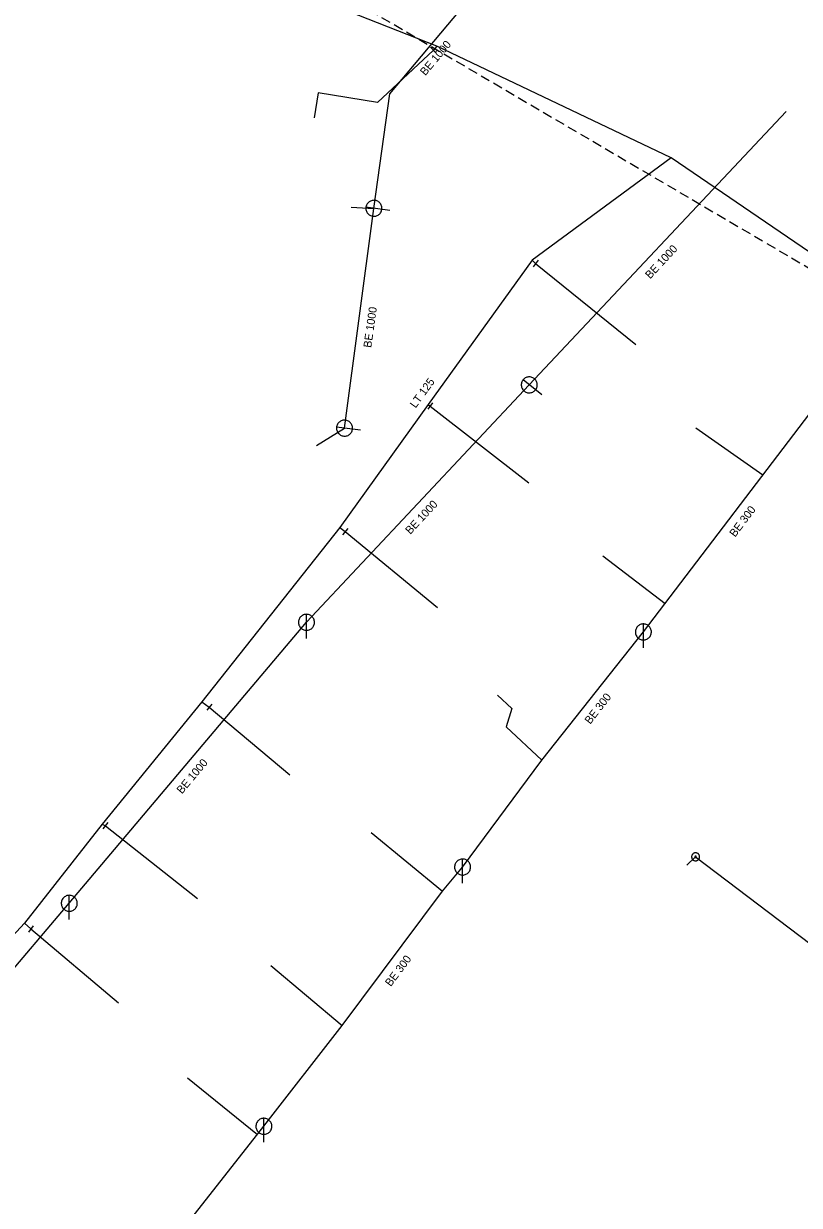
# Model space of a CAD drawing. Extents: x -791337 to -790755, y -988454 to -987923.
# Drawn here: x -790949.7 to -790852.8, y -988262.8 to -988115.1 of the extents above; entities that cross this region are included whole.
import ezdxf

# ---------------------------------------------------------------- set-up
doc = ezdxf.new("R2010")
doc.units = 0
doc.header["$LTSCALE"] = 0.4
doc.linetypes.add('MEDIUM_DASHED', pattern=[4.5, 3, -1.5])
for name, color, linetype, lineweight in [('1', 7, 'Continuous', 13), ('11', 7, 'Continuous', 13), ('13', 7, 'Continuous', 13), ('14', 7, 'Continuous', 25), ('17', 7, 'Continuous', 25), ('22', 7, 'Continuous', 13), ('34', 7, 'Continuous', 13), ('47', 7, 'Continuous', 13), ('63', 7, 'MEDIUM_DASHED', 25)]:
    doc.layers.add(name, color=color, linetype=linetype, lineweight=lineweight)

msp = doc.modelspace()

# ---------------------------------------------------------------- linework, layer by layer
at = {"layer": '11'}
for p, q in [((-790908.772, -988138.055), (-790905.94, -988138.22)), ((-790913.105, -988167.839), (-790909.605, -988165.675)), ((-790865.701, -988165.618), (-790857.318, -988171.518)), ((-790877.322, -988181.627), (-790869.546, -988187.578)), ((-790906.261, -988216.18), (-790897.349, -988223.506)), ((-790918.802, -988232.798), (-790909.899, -988240.304)), ((-790929.23, -988246.811), (-790920.498, -988253.919))]:
    msp.add_line(p, q, dxfattribs=at)
msp.add_lwpolyline([(-790890.491, -988199.037), (-790888.688, -988200.703), (-790889.381, -988202.993), (-790884.943, -988207.155)], dxfattribs=at)
at = {"layer": '13'}
for p, q in [((-790898.061, -988117.949), (-790898.489, -988118.469)), ((-790886.164, -988144.675), (-790885.719, -988145.118)), ((-790885.719, -988145.118), (-790873.182, -988155.239)), ((-790898.901, -988162.913), (-790886.583, -988172.519)), ((-790910.179, -988178.094), (-790909.519, -988178.599)), ((-790909.519, -988178.599), (-790897.998, -988188.059)), ((-790927.416, -988199.874), (-790926.509, -988200.529)), ((-790926.509, -988200.529), (-790916.436, -988208.971)), ((-790939.489, -988215.339), (-790927.989, -988224.438)), ((-790865.725, -988219.221), (-790866.815, -988220.269)), ((-790949.601, -988227.486), (-790948.8, -988228.233)), ((-790948.8, -988228.233), (-790937.833, -988237.469))]:
    msp.add_line(p, q, dxfattribs=at)
msp.add_lwpolyline([(-790898.489, -988118.469), (-790905.469, -988124.98), (-790912.892, -988123.796), (-790913.396, -988126.899)], dxfattribs=at)
at = {"layer": '14'}
for p, q in [((-790886.515, -988160.271), (-790854.399, -988126.109)), ((-790909.605, -988165.675), (-790905.94, -988138.22)), ((-790914.359, -988189.93), (-790886.515, -988160.271)), ((-790872.25, -988191.129), (-790848.859, -988160.41)), ((-790944.001, -988225.028), (-790914.359, -988189.93)), ((-790974.239, -988260.57), (-790944.001, -988225.028)), ((-790944.69, -988284.64), (-790919.68, -988252.879))]:
    msp.add_line(p, q, dxfattribs=at)
at = {"layer": '14', "lineweight": 13}
for p, q in [((-790899.148, -988162.743), (-790898.901, -988162.913)), ((-790939.877, -988215.123), (-790939.489, -988215.339))]:
    msp.add_line(p, q, dxfattribs=at)
at = {"layer": '14'}
for points in [[(-790905.94, -988138.22), (-790903.94, -988123.91), (-790893.6, -988111.609)], [(-790894.85, -988220.5), (-790884.943, -988207.155), (-790872.25, -988191.129)], [(-790919.68, -988252.879), (-790909.899, -988240.304), (-790897.349, -988223.506), (-790894.85, -988220.5)]]:
    msp.add_lwpolyline(points, dxfattribs=at)
at = {"layer": '17'}
for points in [[(-790868.789, -988131.909), (-790898.061, -988117.949), (-790952.1, -988096.67), (-790985.039, -988083.809)], [(-790868.789, -988131.909), (-790886.164, -988144.675), (-790899.148, -988162.743), (-790910.179, -988178.094), (-790927.416, -988199.874), (-790939.877, -988215.123), (-790949.601, -988227.486), (-790953.649, -988231.855), (-790965.795, -988245.864)], [(-790779.549, -988196.869), (-790789.015, -988189.477), (-790807.158, -988175.363), (-790824.261, -988162.25), (-790868.789, -988131.909)], [(-790865.725, -988219.221), (-790850.055, -988231.078), (-790832.26, -988245.158), (-790819.799, -988254.598)]]:
    msp.add_lwpolyline(points, dxfattribs=at)
at = {"layer": '22'}
for p, q in [((-790903.957, -988138.484), (-790906.93, -988138.087)), ((-790884.954, -988161.522), (-790887.294, -988159.645)), ((-790907.622, -988165.939), (-790910.595, -988165.542)), ((-790914.359, -988191.93), (-790914.358, -988188.93)), ((-790872.25, -988193.129), (-790872.249, -988190.129)), ((-790894.85, -988222.5), (-790894.849, -988219.5)), ((-790944.001, -988227.028), (-790944, -988224.028)), ((-790919.68, -988254.879), (-790919.679, -988251.879))]:
    msp.add_line(p, q, dxfattribs=at)
for points in [[(-790905.807, -988137.228), (-790905.915, -988137.22), (-790906.025, -988137.223), (-790906.134, -988137.239), (-790906.239, -988137.265), (-790906.342, -988137.304), (-790906.44, -988137.354), (-790906.532, -988137.414), (-790906.616, -988137.484), (-790906.693, -988137.562), (-790906.76, -988137.648), (-790906.817, -988137.741), (-790906.864, -988137.841), (-790906.9, -988137.944), (-790906.924, -988138.051), (-790906.937, -988138.16), (-790906.937, -988138.269), (-790906.927, -988138.378), (-790906.904, -988138.485), (-790906.868, -988138.589), (-790906.823, -988138.688), (-790906.766, -988138.782), (-790906.7, -988138.869), (-790906.623, -988138.948), (-790906.54, -988139.019), (-790906.449, -988139.08), (-790906.352, -988139.13), (-790906.25, -988139.17), (-790906.144, -988139.198), (-790906.036, -988139.215), (-790905.926, -988139.219), (-790905.817, -988139.212), (-790905.71, -988139.192), (-790905.605, -988139.162), (-790905.503, -988139.12), (-790905.407, -988139.066), (-790905.318, -988139.004), (-790905.236, -988138.931), (-790905.163, -988138.85), (-790905.098, -988138.762), (-790905.044, -988138.666), (-790905.001, -988138.566), (-790904.968, -988138.461), (-790904.948, -988138.353), (-790904.939, -988138.244), (-790904.943, -988138.135), (-790904.958, -988138.027), (-790904.985, -988137.92), (-790905.024, -988137.817), (-790905.073, -988137.72), (-790905.133, -988137.628), (-790905.202, -988137.543), (-790905.281, -988137.467), (-790905.366, -988137.399), (-790905.46, -988137.342), (-790905.558, -988137.295), (-790905.662, -988137.259), (-790905.769, -988137.234)], [(-790885.889, -988159.491), (-790885.977, -988159.427), (-790886.073, -988159.374), (-790886.174, -988159.331), (-790886.278, -988159.299), (-790886.386, -988159.279), (-790886.495, -988159.271), (-790886.605, -988159.275), (-790886.713, -988159.291), (-790886.82, -988159.318), (-790886.921, -988159.357), (-790887.019, -988159.407), (-790887.11, -988159.469), (-790887.194, -988159.538), (-790887.27, -988159.617), (-790887.338, -988159.704), (-790887.394, -988159.797), (-790887.442, -988159.896), (-790887.477, -988160), (-790887.5, -988160.107), (-790887.513, -988160.215), (-790887.513, -988160.325), (-790887.501, -988160.434), (-790887.477, -988160.541), (-790887.442, -988160.645), (-790887.395, -988160.743), (-790887.338, -988160.837), (-790887.271, -988160.924), (-790887.195, -988161.002), (-790887.111, -988161.073), (-790887.02, -988161.133), (-790886.923, -988161.184), (-790886.821, -988161.222), (-790886.715, -988161.25), (-790886.606, -988161.267), (-790886.496, -988161.27), (-790886.388, -988161.263), (-790886.28, -988161.243), (-790886.175, -988161.212), (-790886.074, -988161.169), (-790885.979, -988161.115), (-790885.89, -988161.052), (-790885.808, -988160.979), (-790885.734, -988160.897), (-790885.671, -988160.808), (-790885.617, -988160.713), (-790885.574, -988160.613), (-790885.543, -988160.507), (-790885.523, -988160.399), (-790885.515, -988160.29), (-790885.518, -988160.181), (-790885.534, -988160.072), (-790885.562, -988159.967), (-790885.6, -988159.864), (-790885.65, -988159.767), (-790885.71, -988159.676), (-790885.781, -988159.591), (-790885.86, -988159.515)], [(-790909.472, -988164.683), (-790909.58, -988164.675), (-790909.69, -988164.678), (-790909.799, -988164.694), (-790909.904, -988164.72), (-790910.007, -988164.759), (-790910.105, -988164.809), (-790910.197, -988164.869), (-790910.281, -988164.939), (-790910.358, -988165.017), (-790910.425, -988165.103), (-790910.482, -988165.196), (-790910.529, -988165.296), (-790910.565, -988165.399), (-790910.589, -988165.506), (-790910.602, -988165.615), (-790910.602, -988165.724), (-790910.592, -988165.833), (-790910.569, -988165.94), (-790910.533, -988166.044), (-790910.488, -988166.143), (-790910.431, -988166.237), (-790910.365, -988166.324), (-790910.288, -988166.403), (-790910.205, -988166.474), (-790910.114, -988166.535), (-790910.017, -988166.585), (-790909.915, -988166.625), (-790909.809, -988166.653), (-790909.701, -988166.67), (-790909.591, -988166.674), (-790909.482, -988166.667), (-790909.375, -988166.647), (-790909.27, -988166.617), (-790909.168, -988166.575), (-790909.072, -988166.521), (-790908.983, -988166.459), (-790908.901, -988166.386), (-790908.828, -988166.305), (-790908.763, -988166.217), (-790908.709, -988166.121), (-790908.666, -988166.021), (-790908.633, -988165.916), (-790908.613, -988165.808), (-790908.604, -988165.699), (-790908.608, -988165.59), (-790908.623, -988165.482), (-790908.65, -988165.375), (-790908.689, -988165.272), (-790908.738, -988165.175), (-790908.798, -988165.083), (-790908.867, -988164.998), (-790908.946, -988164.922), (-790909.031, -988164.854), (-790909.125, -988164.797), (-790909.223, -988164.75), (-790909.327, -988164.714), (-790909.434, -988164.689)], [(-790913.359, -988189.93), (-790913.364, -988189.821), (-790913.382, -988189.713), (-790913.412, -988189.607), (-790913.452, -988189.506), (-790913.504, -988189.409), (-790913.566, -988189.319), (-790913.638, -988189.236), (-790913.718, -988189.162), (-790913.806, -988189.096), (-790913.9, -988189.041), (-790914, -988188.996), (-790914.105, -988188.963), (-790914.212, -988188.941), (-790914.321, -988188.931), (-790914.431, -988188.933), (-790914.539, -988188.947), (-790914.646, -988188.972), (-790914.749, -988189.009), (-790914.847, -988189.058), (-790914.939, -988189.116), (-790915.025, -988189.185), (-790915.102, -988189.262), (-790915.171, -988189.348), (-790915.23, -988189.44), (-790915.278, -988189.538), (-790915.315, -988189.641), (-790915.341, -988189.748), (-790915.355, -988189.856), (-790915.358, -988189.966), (-790915.348, -988190.075), (-790915.327, -988190.182), (-790915.293, -988190.286), (-790915.249, -988190.386), (-790915.194, -988190.481), (-790915.128, -988190.569), (-790915.054, -988190.649), (-790914.971, -988190.721), (-790914.881, -988190.783), (-790914.785, -988190.835), (-790914.683, -988190.876), (-790914.578, -988190.906), (-790914.47, -988190.924), (-790914.36, -988190.93), (-790914.251, -988190.924), (-790914.143, -988190.906), (-790914.038, -988190.877), (-790913.936, -988190.836), (-790913.839, -988190.784), (-790913.749, -988190.722), (-790913.666, -988190.651), (-790913.591, -988190.571), (-790913.526, -988190.483), (-790913.47, -988190.389), (-790913.426, -988190.289), (-790913.392, -988190.185), (-790913.37, -988190.077), (-790913.36, -988189.968)], [(-790871.25, -988191.129), (-790871.255, -988191.02), (-790871.273, -988190.912), (-790871.303, -988190.806), (-790871.343, -988190.705), (-790871.395, -988190.608), (-790871.457, -988190.518), (-790871.529, -988190.435), (-790871.609, -988190.361), (-790871.697, -988190.295), (-790871.791, -988190.24), (-790871.891, -988190.195), (-790871.996, -988190.162), (-790872.103, -988190.14), (-790872.212, -988190.13), (-790872.322, -988190.132), (-790872.43, -988190.146), (-790872.537, -988190.171), (-790872.64, -988190.208), (-790872.738, -988190.257), (-790872.83, -988190.315), (-790872.916, -988190.384), (-790872.993, -988190.461), (-790873.062, -988190.547), (-790873.121, -988190.639), (-790873.169, -988190.737), (-790873.206, -988190.84), (-790873.232, -988190.947), (-790873.246, -988191.055), (-790873.249, -988191.165), (-790873.239, -988191.274), (-790873.218, -988191.381), (-790873.184, -988191.485), (-790873.14, -988191.585), (-790873.085, -988191.68), (-790873.019, -988191.768), (-790872.945, -988191.848), (-790872.862, -988191.92), (-790872.772, -988191.982), (-790872.676, -988192.034), (-790872.574, -988192.075), (-790872.469, -988192.105), (-790872.361, -988192.123), (-790872.251, -988192.129), (-790872.142, -988192.123), (-790872.034, -988192.105), (-790871.929, -988192.076), (-790871.827, -988192.035), (-790871.73, -988191.983), (-790871.64, -988191.921), (-790871.557, -988191.85), (-790871.482, -988191.77), (-790871.417, -988191.682), (-790871.361, -988191.588), (-790871.317, -988191.488), (-790871.283, -988191.384), (-790871.261, -988191.276), (-790871.251, -988191.167)], [(-790893.85, -988220.5), (-790893.855, -988220.391), (-790893.873, -988220.283), (-790893.903, -988220.177), (-790893.943, -988220.076), (-790893.995, -988219.979), (-790894.057, -988219.889), (-790894.129, -988219.806), (-790894.209, -988219.732), (-790894.297, -988219.666), (-790894.391, -988219.611), (-790894.491, -988219.566), (-790894.596, -988219.533), (-790894.703, -988219.511), (-790894.812, -988219.501), (-790894.922, -988219.503), (-790895.03, -988219.517), (-790895.137, -988219.542), (-790895.24, -988219.579), (-790895.338, -988219.628), (-790895.43, -988219.686), (-790895.516, -988219.755), (-790895.593, -988219.832), (-790895.662, -988219.918), (-790895.721, -988220.01), (-790895.769, -988220.108), (-790895.806, -988220.211), (-790895.832, -988220.318), (-790895.846, -988220.426), (-790895.849, -988220.536), (-790895.839, -988220.645), (-790895.818, -988220.752), (-790895.784, -988220.856), (-790895.74, -988220.956), (-790895.685, -988221.051), (-790895.619, -988221.139), (-790895.545, -988221.219), (-790895.462, -988221.291), (-790895.372, -988221.353), (-790895.276, -988221.405), (-790895.174, -988221.446), (-790895.069, -988221.476), (-790894.961, -988221.494), (-790894.851, -988221.5), (-790894.742, -988221.494), (-790894.634, -988221.476), (-790894.529, -988221.447), (-790894.427, -988221.406), (-790894.33, -988221.354), (-790894.24, -988221.292), (-790894.157, -988221.221), (-790894.082, -988221.141), (-790894.017, -988221.053), (-790893.961, -988220.959), (-790893.917, -988220.859), (-790893.883, -988220.755), (-790893.861, -988220.647), (-790893.851, -988220.538)], [(-790943.001, -988225.028), (-790943.006, -988224.919), (-790943.024, -988224.811), (-790943.054, -988224.705), (-790943.094, -988224.604), (-790943.146, -988224.507), (-790943.208, -988224.417), (-790943.28, -988224.334), (-790943.36, -988224.26), (-790943.448, -988224.194), (-790943.542, -988224.139), (-790943.642, -988224.094), (-790943.747, -988224.061), (-790943.854, -988224.039), (-790943.963, -988224.029), (-790944.073, -988224.031), (-790944.181, -988224.045), (-790944.288, -988224.07), (-790944.391, -988224.107), (-790944.489, -988224.156), (-790944.581, -988224.214), (-790944.667, -988224.283), (-790944.744, -988224.36), (-790944.813, -988224.446), (-790944.872, -988224.538), (-790944.92, -988224.636), (-790944.957, -988224.739), (-790944.983, -988224.846), (-790944.997, -988224.954), (-790945, -988225.064), (-790944.99, -988225.173), (-790944.969, -988225.28), (-790944.935, -988225.384), (-790944.891, -988225.484), (-790944.836, -988225.579), (-790944.77, -988225.667), (-790944.696, -988225.747), (-790944.613, -988225.819), (-790944.523, -988225.881), (-790944.427, -988225.933), (-790944.325, -988225.974), (-790944.22, -988226.004), (-790944.112, -988226.022), (-790944.002, -988226.028), (-790943.893, -988226.022), (-790943.785, -988226.004), (-790943.68, -988225.975), (-790943.578, -988225.934), (-790943.481, -988225.882), (-790943.391, -988225.82), (-790943.308, -988225.749), (-790943.233, -988225.669), (-790943.168, -988225.581), (-790943.112, -988225.487), (-790943.068, -988225.387), (-790943.034, -988225.283), (-790943.012, -988225.175), (-790943.002, -988225.066)], [(-790918.68, -988252.879), (-790918.685, -988252.77), (-790918.703, -988252.662), (-790918.733, -988252.556), (-790918.773, -988252.455), (-790918.825, -988252.358), (-790918.887, -988252.268), (-790918.959, -988252.185), (-790919.039, -988252.111), (-790919.127, -988252.045), (-790919.221, -988251.99), (-790919.321, -988251.945), (-790919.426, -988251.912), (-790919.533, -988251.89), (-790919.642, -988251.88), (-790919.752, -988251.882), (-790919.86, -988251.896), (-790919.967, -988251.921), (-790920.07, -988251.958), (-790920.168, -988252.007), (-790920.26, -988252.065), (-790920.346, -988252.134), (-790920.423, -988252.211), (-790920.492, -988252.297), (-790920.551, -988252.389), (-790920.599, -988252.487), (-790920.636, -988252.59), (-790920.662, -988252.697), (-790920.676, -988252.805), (-790920.679, -988252.915), (-790920.669, -988253.024), (-790920.648, -988253.131), (-790920.614, -988253.235), (-790920.57, -988253.335), (-790920.515, -988253.43), (-790920.449, -988253.518), (-790920.375, -988253.598), (-790920.292, -988253.67), (-790920.202, -988253.732), (-790920.106, -988253.784), (-790920.004, -988253.825), (-790919.899, -988253.855), (-790919.791, -988253.873), (-790919.681, -988253.879), (-790919.572, -988253.873), (-790919.464, -988253.855), (-790919.359, -988253.826), (-790919.257, -988253.785), (-790919.16, -988253.733), (-790919.07, -988253.671), (-790918.987, -988253.6), (-790918.912, -988253.52), (-790918.847, -988253.432), (-790918.791, -988253.338), (-790918.747, -988253.238), (-790918.713, -988253.134), (-790918.691, -988253.026), (-790918.681, -988252.917)]]:
    msp.add_lwpolyline(points, close=True, dxfattribs=at)
at = {"layer": '34'}
for p, q in [((-790898.837, -988118.11), (-790898.141, -988118.828)), ((-790885.422, -988144.715), (-790886.016, -988145.52)), ((-790898.619, -988162.499), (-790899.183, -988163.325)), ((-790909.199, -988178.214), (-790909.839, -988178.982)), ((-790926.192, -988200.141), (-790926.826, -988200.915)), ((-790939.179, -988214.946), (-790939.799, -988215.731)), ((-790948.499, -988227.833), (-790949.101, -988228.631))]:
    msp.add_line(p, q, dxfattribs=at)
at = {"layer": '47'}
for points in [[(-790865.326, -988219.522), (-790865.297, -988219.479), (-790865.272, -988219.433), (-790865.253, -988219.384), (-790865.238, -988219.334), (-790865.228, -988219.282), (-790865.225, -988219.23), (-790865.227, -988219.178), (-790865.234, -988219.126), (-790865.246, -988219.076), (-790865.264, -988219.026), (-790865.287, -988218.979), (-790865.315, -988218.935), (-790865.347, -988218.893), (-790865.383, -988218.856), (-790865.423, -988218.822), (-790865.466, -988218.793), (-790865.512, -988218.768), (-790865.562, -988218.748), (-790865.611, -988218.734), (-790865.663, -988218.724), (-790865.715, -988218.721), (-790865.768, -988218.723), (-790865.82, -988218.73), (-790865.87, -988218.742), (-790865.919, -988218.76), (-790865.966, -988218.783), (-790866.011, -988218.81), (-790866.052, -988218.843), (-790866.089, -988218.879), (-790866.123, -988218.919), (-790866.152, -988218.962), (-790866.177, -988219.008), (-790866.198, -988219.057), (-790866.211, -988219.107), (-790866.221, -988219.159), (-790866.225, -988219.211), (-790866.223, -988219.263), (-790866.216, -988219.315), (-790866.203, -988219.366), (-790866.185, -988219.415), (-790866.162, -988219.462), (-790866.135, -988219.507), (-790866.102, -988219.548), (-790866.066, -988219.585), (-790866.026, -988219.619), (-790865.983, -988219.648), (-790865.937, -988219.673), (-790865.889, -988219.693), (-790865.838, -988219.707), (-790865.786, -988219.717), (-790865.734, -988219.721), (-790865.683, -988219.719), (-790865.631, -988219.711), (-790865.58, -988219.699), (-790865.53, -988219.681), (-790865.483, -988219.658), (-790865.439, -988219.631), (-790865.397, -988219.598), (-790865.36, -988219.562)], [(-790865.659, -988219.27), (-790865.654, -988219.263), (-790865.65, -988219.255), (-790865.647, -988219.248), (-790865.645, -988219.239), (-790865.643, -988219.231), (-790865.643, -988219.222), (-790865.643, -988219.213), (-790865.644, -988219.205), (-790865.646, -988219.197), (-790865.649, -988219.189), (-790865.653, -988219.181), (-790865.658, -988219.173), (-790865.663, -988219.167), (-790865.668, -988219.161), (-790865.675, -988219.155), (-790865.682, -988219.15), (-790865.69, -988219.146), (-790865.697, -988219.143), (-790865.706, -988219.141), (-790865.714, -988219.139), (-790865.723, -988219.139), (-790865.732, -988219.139), (-790865.74, -988219.14), (-790865.749, -988219.142), (-790865.756, -988219.145), (-790865.764, -988219.149), (-790865.772, -988219.154), (-790865.778, -988219.159), (-790865.784, -988219.164), (-790865.79, -988219.171), (-790865.795, -988219.178), (-790865.799, -988219.186), (-790865.802, -988219.193), (-790865.804, -988219.202), (-790865.806, -988219.21), (-790865.807, -988219.218), (-790865.806, -988219.228), (-790865.805, -988219.236), (-790865.803, -988219.245), (-790865.8, -988219.252), (-790865.796, -988219.26), (-790865.791, -988219.268), (-790865.786, -988219.274), (-790865.781, -988219.28), (-790865.774, -988219.286), (-790865.767, -988219.291), (-790865.759, -988219.295), (-790865.752, -988219.298), (-790865.743, -988219.3), (-790865.735, -988219.302), (-790865.727, -988219.303), (-790865.717, -988219.302), (-790865.709, -988219.301), (-790865.701, -988219.299), (-790865.693, -988219.296), (-790865.685, -988219.292), (-790865.677, -988219.287), (-790865.671, -988219.282), (-790865.665, -988219.277)]]:
    msp.add_lwpolyline(points, close=True, dxfattribs=at)
at = {"layer": '63'}
msp.add_lwpolyline([(-791231.02, -987923.132), (-790755.118, -988202.253), (-790755.118, -988202.253), (-790903.053, -988400.429), (-790903.053, -988400.429), (-791331.504, -988073.857), (-791331.504, -988073.857)], close=True, dxfattribs=at)

# ---------------------------------------------------------------- texts
at = {"layer": '1'}
for s, rotation, p in [('BE 1000 ', 50, (-790899.502, -988121.716)), ('BE 1000 ', 47, (-790871.408, -988147.1)), ('BE 1000 ', 82, (-790906.267, -988155.679)), ('LT 125', 54, (-790900.722, -988163.245)), ('BE 1000 ', 47, (-790901.385, -988179.01)), ('BE 300', 53, (-790860.792, -988179.358)), ('BE 300', 52, (-790878.902, -988202.726)), ('BE 1000 ', 50, (-790929.921, -988211.433)), ('BE 300', 53, (-790903.829, -988235.496))]:
    msp.add_text(s, height=1, rotation=rotation, dxfattribs=at).set_placement(p)

doc.saveas('drawing.dxf')
